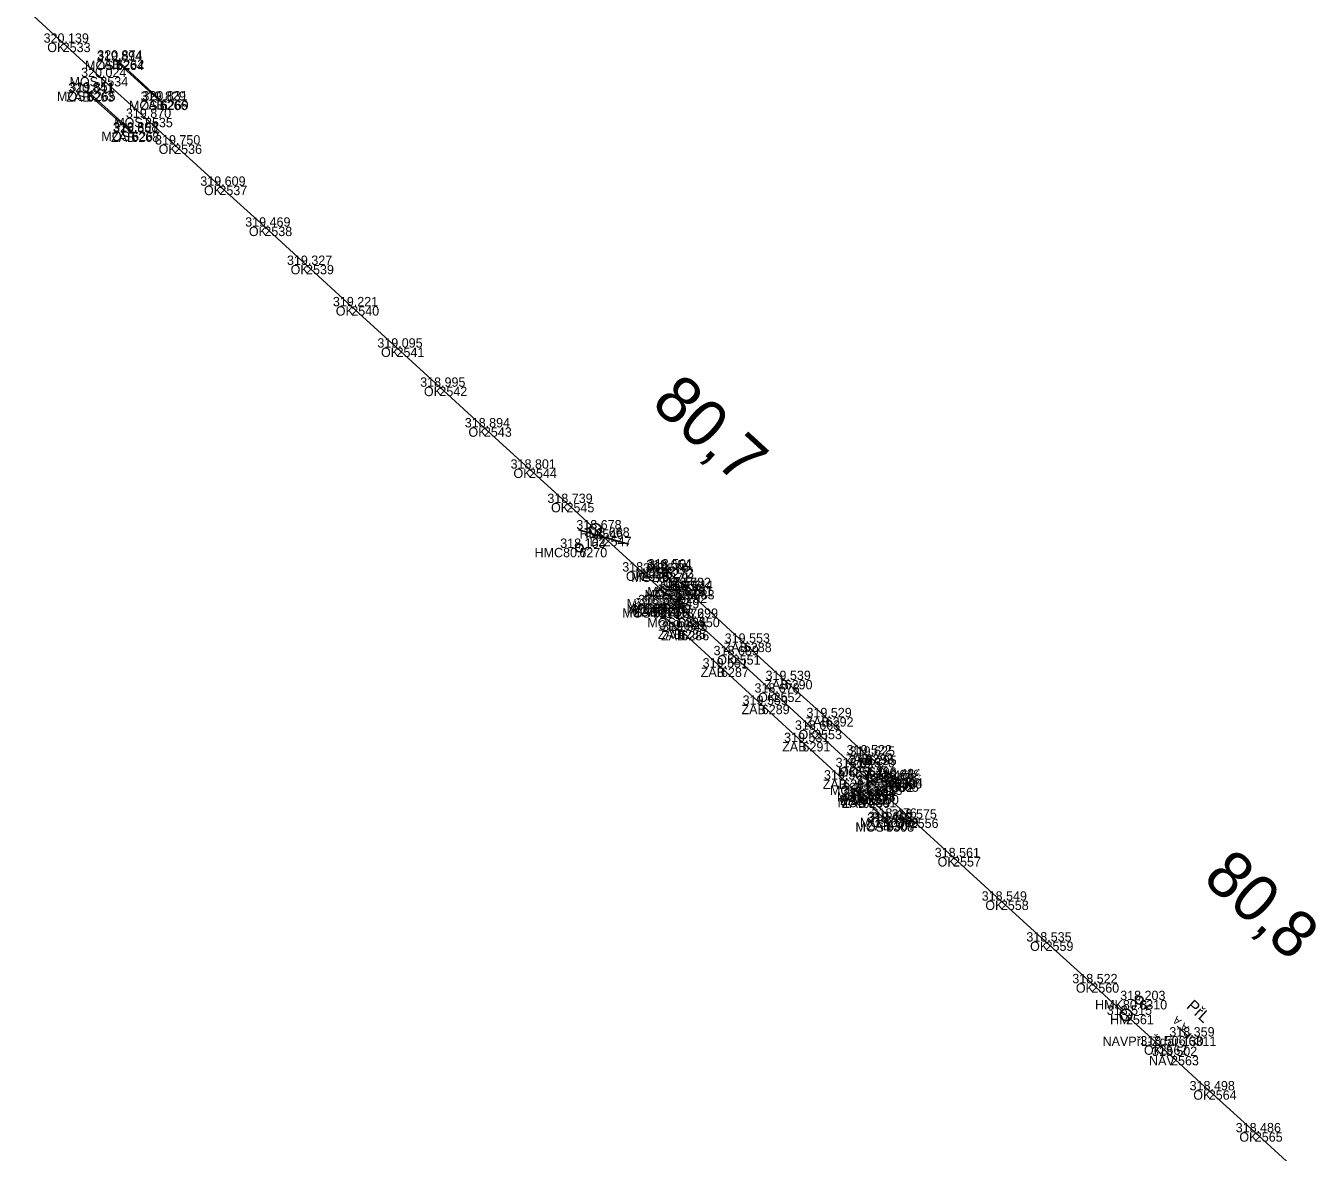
# Model space of a CAD drawing. Extents: x -621782 to -610392, y -1141853 to -1122321.
# Drawn here: x -614148.7 to -613983.2, y -1130727.2 to -1130582.8 of the extents above; entities that cross this region are included whole.
import ezdxf

# ---------------------------------------------------------------- set-up
doc = ezdxf.new("R2010")
doc.units = 0
for name, color, linetype in [('Vrstva 1', 7, 'Continuous'), ('Vrstva 17', 7, 'Continuous'), ('Vrstva 18', 7, 'Continuous'), ('Vrstva 3', 7, 'Continuous'), ('Vrstva 6', 7, 'Continuous'), ('Vrstva 60', 7, 'Continuous'), ('Vrstva 61', 7, 'Continuous'), ('Vrstva 62', 7, 'Continuous'), ('Vrstva 7', 7, 'Continuous')]:
    doc.layers.add(name, color=color, linetype=linetype)

msp = doc.modelspace()

# ---------------------------------------------------------------- linework, layer by layer
at = {"layer": 'Vrstva 1'}
msp.add_lwpolyline([(-614148.65, -1130580.61), (-614143.92, -1130584.95), (-614139.1, -1130589.35), (-614133.37, -1130594.58), (-614129.63, -1130598), (-614123.83, -1130603.29), (-614118.07, -1130608.53), (-614112.72, -1130613.44), (-614106.92, -1130618.74), (-614101.12, -1130624.04), (-614095.63, -1130629.06), (-614089.92, -1130634.27), (-614084.14, -1130639.56), (-614079.33, -1130643.96), (-614075.61, -1130647.35), (-614074.57, -1130648.3), (-614069.72, -1130652.75), (-614065.88, -1130656.27), (-614063.25, -1130658.68), (-614058.02, -1130663.48), (-614052.78, -1130668.28), (-614047.59, -1130673.04), (-614042.37, -1130677.84), (-614039.82, -1130680.19), (-614035.2, -1130684.43), (-614029.77, -1130689.38), (-614023.64, -1130694.95), (-614017.91, -1130700.19), (-614012.04, -1130705.54), (-614007.6, -1130709.59), (-614003.3, -1130713.51), (-614001.82, -1130714.86), (-613996.98, -1130719.27), (-613991.08, -1130724.65), (-613985.5, -1130729.75)], dxfattribs=at)
at = {"layer": 'Vrstva 17'}
for p, q in [((-614137.04, -1130587.11), (-614131.35, -1130592.35)), ((-614135.12, -1130596.46), (-614140.86, -1130591.31))]:
    msp.add_line(p, q, dxfattribs=at)
for points in [[(-614066.66, -1130652.45), (-614064.17, -1130654.74), (-614063.92, -1130655.12), (-614056.6, -1130661.88), (-614051.36, -1130666.66), (-614046.1, -1130671.43), (-614040.97, -1130676.2), (-614040.57, -1130676.37), (-614037.32, -1130679.37)], [(-614038.21, -1130684.75), (-614041.4, -1130681.85), (-614041.64, -1130681.47), (-614043.86, -1130679.42), (-614049.07, -1130674.62), (-614054.29, -1130669.84), (-614059.52, -1130665.06), (-614064.61, -1130660.37), (-614065.02, -1130660.19), (-614068.12, -1130657.34)]]:
    msp.add_lwpolyline(points, dxfattribs=at)
at = {"layer": 'Vrstva 18'}
for p, q in [((-614131.47, -1130592.39), (-614137.1, -1130587.25)), ((-614140.71, -1130591.21), (-614135.02, -1130596.34))]:
    msp.add_line(p, q, dxfattribs=at)
for points in [[(-614066.56, -1130652.36), (-614067.07, -1130652.89), (-614065.05, -1130654.75), (-614065.38, -1130655.11), (-614064.88, -1130655.58), (-614065.03, -1130658.7), (-614066.97, -1130656.92), (-614067.31, -1130657.28), (-614067.68, -1130656.94), (-614068.23, -1130657.46)], [(-614038.33, -1130684.9), (-614037.77, -1130684.31), (-614040.61, -1130681.77), (-614040.29, -1130681.4), (-614040.72, -1130681.03), (-614040.57, -1130677.86), (-614038.44, -1130679.81), (-614038.08, -1130679.45), (-614037.73, -1130679.79), (-614037.22, -1130679.25)]]:
    msp.add_lwpolyline(points, dxfattribs=at)
at = {"layer": 'Vrstva 3'}
msp.add_line((-614077.8, -1130647.39), (-614071.35, -1130649.22), dxfattribs=at)
at = {"layer": 'Vrstva 6'}
for p, q in [((-614001.05, -1130711.04), (-613999.58, -1130712.37)), ((-613999.92, -1130712.74), (-613999.25, -1130712))]:
    msp.add_line(p, q, dxfattribs=at)
at = {"layer": 'Vrstva 60'}
for p, q in [((-614143.92, -1130584.95), (-614143.92, -1130584.95)), ((-614137.1, -1130587.25), (-614137.1, -1130587.25)), ((-614137.04, -1130587.11), (-614137.04, -1130587.11)), ((-614139.1, -1130589.35), (-614139.1, -1130589.35)), ((-614140.86, -1130591.31), (-614140.86, -1130591.31)), ((-614140.71, -1130591.21), (-614140.71, -1130591.21)), ((-614131.47, -1130592.39), (-614131.47, -1130592.39)), ((-614131.35, -1130592.35), (-614131.35, -1130592.35)), ((-614133.37, -1130594.58), (-614133.37, -1130594.58)), ((-614135.12, -1130596.46), (-614135.12, -1130596.46)), ((-614135.02, -1130596.34), (-614135.02, -1130596.34)), ((-614129.63, -1130598), (-614129.63, -1130598)), ((-614123.83, -1130603.29), (-614123.83, -1130603.29)), ((-614118.07, -1130608.53), (-614118.07, -1130608.53)), ((-614112.72, -1130613.44), (-614112.72, -1130613.44)), ((-614106.92, -1130618.74), (-614106.92, -1130618.74)), ((-614101.12, -1130624.04), (-614101.12, -1130624.04)), ((-614095.63, -1130629.06), (-614095.63, -1130629.06)), ((-614089.92, -1130634.27), (-614089.92, -1130634.27)), ((-614084.14, -1130639.56), (-614084.14, -1130639.56)), ((-614079.33, -1130643.96), (-614079.33, -1130643.96)), ((-614075.61, -1130647.35), (-614075.61, -1130647.35)), ((-614074.57, -1130648.3), (-614074.57, -1130648.3)), ((-614077.68, -1130649.72), (-614077.68, -1130649.72)), ((-614066.66, -1130652.45), (-614066.66, -1130652.45)), ((-614066.56, -1130652.36), (-614066.56, -1130652.36)), ((-614069.72, -1130652.75), (-614069.72, -1130652.75)), ((-614067.07, -1130652.89), (-614067.07, -1130652.89)), ((-614065.38, -1130655.11), (-614065.38, -1130655.11)), ((-614065.05, -1130654.75), (-614065.05, -1130654.75)), ((-614064.88, -1130655.58), (-614064.88, -1130655.58)), ((-614064.17, -1130654.74), (-614064.17, -1130654.74)), ((-614063.92, -1130655.12), (-614063.92, -1130655.12)), ((-614068.23, -1130657.46), (-614068.23, -1130657.46)), ((-614068.12, -1130657.34), (-614068.12, -1130657.34)), ((-614067.68, -1130656.94), (-614067.68, -1130656.94)), ((-614067.31, -1130657.28), (-614067.31, -1130657.28)), ((-614066.97, -1130656.92), (-614066.97, -1130656.92)), ((-614065.88, -1130656.27), (-614065.88, -1130656.27)), ((-614065.03, -1130658.7), (-614065.03, -1130658.7)), ((-614063.25, -1130658.68), (-614063.25, -1130658.68)), ((-614065.02, -1130660.19), (-614065.02, -1130660.19)), ((-614064.61, -1130660.37), (-614064.61, -1130660.37)), ((-614056.6, -1130661.88), (-614056.6, -1130661.88)), ((-614058.02, -1130663.48), (-614058.02, -1130663.48)), ((-614059.52, -1130665.06), (-614059.52, -1130665.06)), ((-614051.36, -1130666.66), (-614051.36, -1130666.66)), ((-614052.78, -1130668.28), (-614052.78, -1130668.28)), ((-614054.29, -1130669.84), (-614054.29, -1130669.84)), ((-614046.1, -1130671.43), (-614046.1, -1130671.43)), ((-614047.59, -1130673.04), (-614047.59, -1130673.04)), ((-614049.07, -1130674.62), (-614049.07, -1130674.62)), ((-614040.97, -1130676.2), (-614040.97, -1130676.2)), ((-614040.57, -1130676.37), (-614040.57, -1130676.37)), ((-614042.37, -1130677.84), (-614042.37, -1130677.84)), ((-614040.57, -1130677.86), (-614040.57, -1130677.86)), ((-614043.86, -1130679.42), (-614043.86, -1130679.42)), ((-614039.82, -1130680.19), (-614039.82, -1130680.19)), ((-614038.44, -1130679.81), (-614038.44, -1130679.81)), ((-614038.08, -1130679.45), (-614038.08, -1130679.45)), ((-614037.73, -1130679.79), (-614037.73, -1130679.79)), ((-614037.32, -1130679.37), (-614037.32, -1130679.37)), ((-614037.22, -1130679.25), (-614037.22, -1130679.25)), ((-614041.64, -1130681.47), (-614041.64, -1130681.47)), ((-614041.4, -1130681.85), (-614041.4, -1130681.85)), ((-614040.72, -1130681.03), (-614040.72, -1130681.03)), ((-614040.61, -1130681.77), (-614040.61, -1130681.77)), ((-614040.29, -1130681.4), (-614040.29, -1130681.4)), ((-614038.33, -1130684.9), (-614038.33, -1130684.9)), ((-614038.21, -1130684.75), (-614038.21, -1130684.75)), ((-614037.77, -1130684.31), (-614037.77, -1130684.31)), ((-614035.2, -1130684.43), (-614035.2, -1130684.43)), ((-614029.77, -1130689.38), (-614029.77, -1130689.38)), ((-614023.64, -1130694.95), (-614023.64, -1130694.95)), ((-614017.91, -1130700.19), (-614017.91, -1130700.19)), ((-614012.04, -1130705.54), (-614012.04, -1130705.54)), ((-614005.89, -1130707.7), (-614005.89, -1130707.7)), ((-614007.6, -1130709.59), (-614007.6, -1130709.59)), ((-614003.3, -1130713.51), (-614003.3, -1130713.51)), ((-613999.58, -1130712.37), (-613999.58, -1130712.37)), ((-614001.82, -1130714.86), (-614001.82, -1130714.86)), ((-613996.98, -1130719.27), (-613996.98, -1130719.27)), ((-613991.08, -1130724.65), (-613991.08, -1130724.65))]:
    msp.add_line(p, q, dxfattribs=at)
at = {"layer": 'Vrstva 7'}
for p, q in [((-614077.72, -1130649.69), (-614077.64, -1130649.76)), ((-614005.93, -1130707.67), (-614005.85, -1130707.74))]:
    msp.add_line(p, q, dxfattribs=at)
for centre, radius in [((-614075.61, -1130647.35), 0.75), ((-614077.68, -1130649.72), 0.5), ((-614005.89, -1130707.7), 0.5), ((-614007.6, -1130709.59), 0.75)]:
    msp.add_circle(centre, radius, dxfattribs=at)

# ---------------------------------------------------------------- texts
at = {"layer": 'Vrstva 6'}
for s, height, rotation, p in [('PřL', 1.5, 317.7069, (-613999.94, -1130708.62)), ('  A A ', 1, 137.7069, (-613998.91, -1130711.63))]:
    msp.add_text(s, height=height, rotation=rotation, dxfattribs=at).set_placement(p)
at = {"layer": 'Vrstva 60'}
for s, p in [('2533', (-614143.92, -1130586.15)), ('6264', (-614137.1, -1130588.45)), ('6262', (-614137.04, -1130588.31)), ('2534', (-614139.1, -1130590.55)), ('6263', (-614140.86, -1130592.51)), ('6265', (-614140.71, -1130592.41)), ('6266', (-614131.47, -1130593.59)), ('6269', (-614131.35, -1130593.55)), ('2535', (-614133.37, -1130595.78)), ('6267', (-614135.02, -1130597.54)), ('6268', (-614135.12, -1130597.66)), ('2536', (-614129.63, -1130599.2)), ('2537', (-614123.83, -1130604.49)), ('2538', (-614118.07, -1130609.74)), ('2539', (-614112.72, -1130614.64)), ('2540', (-614106.92, -1130619.94)), ('2541', (-614101.12, -1130625.24)), ('2542', (-614095.63, -1130630.26)), ('2543', (-614089.92, -1130635.47)), ('2544', (-614084.14, -1130640.76)), ('2545', (-614079.33, -1130645.16)), ('2546', (-614075.61, -1130648.55)), ('2547', (-614074.57, -1130649.5)), ('6270', (-614077.68, -1130650.92)), ('6272', (-614066.66, -1130653.65)), ('6273', (-614066.56, -1130653.56)), ('2548', (-614069.72, -1130653.95)), ('6271', (-614067.07, -1130654.09)), ('6277', (-614065.38, -1130656.31)), ('6278', (-614065.05, -1130655.95)), ('6282', (-614064.88, -1130656.78)), ('6281', (-614064.17, -1130655.94)), ('6283', (-614063.92, -1130656.32)), ('6274', (-614068.23, -1130658.66)), ('6275', (-614068.12, -1130658.54)), ('6276', (-614067.68, -1130658.14)), ('6279', (-614067.31, -1130658.48)), ('6280', (-614066.97, -1130658.12)), ('2549', (-614065.88, -1130657.47)), ('6284', (-614065.03, -1130659.9)), ('2550', (-614063.25, -1130659.88)), ('6285', (-614065.02, -1130661.39)), ('6286', (-614064.61, -1130661.57)), ('6288', (-614056.6, -1130663.08)), ('2551', (-614058.02, -1130664.68)), ('6287', (-614059.52, -1130666.26)), ('6290', (-614051.36, -1130667.86)), ('2552', (-614052.78, -1130669.48)), ('6289', (-614054.29, -1130671.04)), ('6292', (-614046.1, -1130672.63)), ('2553', (-614047.59, -1130674.25)), ('6291', (-614049.07, -1130675.82)), ('6293', (-614040.97, -1130677.4)), ('6295', (-614040.57, -1130677.57)), ('2554', (-614042.37, -1130679.04)), ('6296', (-614040.57, -1130679.06)), ('6294', (-614043.86, -1130680.62)), ('2555', (-614039.82, -1130681.39)), ('6302', (-614038.44, -1130681.01)), ('6303', (-614038.08, -1130680.65)), ('6305', (-614037.73, -1130680.99)), ('6306', (-614037.32, -1130680.57)), ('6304', (-614037.22, -1130680.45)), ('6297', (-614041.64, -1130682.67)), ('6299', (-614041.4, -1130683.05)), ('6298', (-614040.72, -1130682.23)), ('6301', (-614040.61, -1130682.97)), ('6300', (-614040.29, -1130682.6)), ('6308', (-614038.33, -1130686.1)), ('6307', (-614038.21, -1130685.95)), ('6309', (-614037.77, -1130685.51)), ('2556', (-614035.2, -1130685.63)), ('2557', (-614029.77, -1130690.57)), ('2558', (-614023.64, -1130696.15)), ('2559', (-614017.91, -1130701.39)), ('2560', (-614012.04, -1130706.75)), ('6310', (-614005.89, -1130708.9)), ('2561', (-614007.6, -1130710.79)), ('2562', (-614003.3, -1130714.71)), ('6311', (-613999.58, -1130713.57)), ('2563', (-614001.82, -1130716.06)), ('2564', (-613996.98, -1130720.47)), ('2565', (-613991.08, -1130725.85))]:
    msp.add_text(s, height=1.2, dxfattribs=at).set_placement(p)
at = {"layer": 'Vrstva 61'}
for s, p in [('320.139', (-614146.37, -1130584.95)), ('319.894', (-614139.55, -1130587.25)), ('320.874', (-614139.49, -1130587.11)), ('320.024', (-614141.56, -1130589.35)), ('320.841', (-614143.22, -1130591.31)), ('319.851', (-614143.07, -1130591.21)), ('319.829', (-614133.93, -1130592.39)), ('320.831', (-614133.7, -1130592.35)), ('319.870', (-614135.82, -1130594.58)), ('320.851', (-614137.48, -1130596.46)), ('319.808', (-614137.47, -1130596.34)), ('319.750', (-614132.08, -1130598)), ('319.609', (-614126.28, -1130603.29)), ('319.469', (-614120.52, -1130608.53)), ('319.327', (-614115.17, -1130613.44)), ('319.221', (-614109.28, -1130618.74)), ('319.095', (-614103.58, -1130624.04)), ('318.995', (-614098.09, -1130629.06)), ('318.894', (-614092.37, -1130634.27)), ('318.801', (-614086.5, -1130639.56)), ('318.739', (-614081.78, -1130643.96)), ('318.678', (-614078.07, -1130647.35)), ('318.668', (-614077.03, -1130648.3)), ('318.163', (-614080.13, -1130649.72)), ('318.669', (-614072.18, -1130652.75)), ('318.570', (-614069.52, -1130652.89)), ('319.654', (-614069.11, -1130652.45)), ('318.501', (-614068.91, -1130652.36)), ('318.566', (-614067.83, -1130655.11)), ('318.578', (-614067.5, -1130654.75)), ('319.682', (-614066.62, -1130654.74)), ('319.544', (-614066.37, -1130655.12)), ('318.566', (-614070.14, -1130656.94)), ('318.565', (-614069.42, -1130656.92)), ('318.698', (-614068.33, -1130656.27)), ('318.573', (-614067.33, -1130655.58)), ('318.509', (-614070.69, -1130657.46)), ('319.659', (-614070.57, -1130657.34)), ('318.562', (-614069.76, -1130657.28)), ('318.572', (-614067.48, -1130658.7)), ('318.699', (-614065.7, -1130658.68)), ('319.680', (-614067.47, -1130660.19)), ('319.545', (-614067.07, -1130660.37)), ('319.553', (-614059.05, -1130661.88)), ('318.689', (-614060.47, -1130663.48)), ('319.551', (-614061.87, -1130665.06)), ('319.539', (-614053.81, -1130666.66)), ('318.678', (-614055.23, -1130668.28)), ('319.559', (-614056.75, -1130669.84)), ('319.529', (-614048.56, -1130671.43)), ('318.663', (-614050.04, -1130673.04)), ('319.531', (-614051.43, -1130674.62)), ('319.522', (-614043.42, -1130676.2)), ('319.625', (-614043.02, -1130676.37)), ('318.643', (-614044.82, -1130677.84)), ('318.520', (-614043.02, -1130677.86)), ('319.503', (-614046.32, -1130679.42)), ('318.631', (-614042.17, -1130680.19)), ('318.475', (-614040.9, -1130679.81)), ('318.475', (-614040.54, -1130679.45)), ('318.478', (-614040.18, -1130679.79)), ('319.618', (-614039.78, -1130679.37)), ('318.484', (-614039.67, -1130679.25)), ('319.522', (-614044.08, -1130681.47)), ('319.634', (-614043.85, -1130681.85)), ('318.511', (-614043.08, -1130681.03)), ('318.504', (-614043.06, -1130681.77)), ('318.510', (-614042.74, -1130681.4)), ('318.463', (-614040.78, -1130684.9)), ('319.602', (-614040.66, -1130684.75)), ('318.476', (-614040.22, -1130684.31)), ('318.575', (-614037.65, -1130684.43)), ('318.561', (-614032.12, -1130689.38)), ('318.549', (-614026.1, -1130694.95)), ('318.535', (-614020.37, -1130700.19)), ('318.522', (-614014.48, -1130705.54)), ('318.203', (-614008.34, -1130707.7)), ('318.515', (-614010.06, -1130709.59)), ('318.359', (-614002.04, -1130712.37)), ('318.506', (-614005.76, -1130713.51)), ('318.502', (-614004.27, -1130714.86)), ('318.498', (-613999.44, -1130719.27)), ('318.486', (-613993.53, -1130724.65))]:
    msp.add_text(s, height=1.2, dxfattribs=at).set_placement(p)
at = {"layer": 'Vrstva 62'}
for s, p in [('OK', (-614145.9, -1130586.15)), ('MOST', (-614141.05, -1130588.45)), ('ZAB', (-614139.64, -1130588.31)), ('MOST', (-614143.05, -1130590.55)), ('MOST', (-614144.66, -1130592.41)), ('ZAB', (-614143.46, -1130592.51)), ('MOST', (-614135.42, -1130593.59)), ('ZAB', (-614133.95, -1130593.55)), ('MOST', (-614137.32, -1130595.78)), ('MOST', (-614138.96, -1130597.54)), ('ZAB', (-614137.72, -1130597.66)), ('OK', (-614131.62, -1130599.2)), ('OK', (-614125.81, -1130604.49)), ('OK', (-614120.05, -1130609.74)), ('OK', (-614114.7, -1130614.64)), ('OK', (-614108.91, -1130619.94)), ('OK', (-614103.11, -1130625.24)), ('OK', (-614097.61, -1130630.26)), ('OK', (-614091.9, -1130635.47)), ('OK', (-614086.13, -1130640.76)), ('OK', (-614081.31, -1130645.16)), ('HM', (-614077.65, -1130648.55)), ('DZ', (-614076.37, -1130649.5)), ('HMC80.7', (-614083.42, -1130650.92)), ('MOST', (-614070.5, -1130653.56)), ('ZAB', (-614069.26, -1130653.65)), ('OK', (-614071.71, -1130653.95)), ('MOST', (-614071.01, -1130654.09)), ('MOST', (-614069.33, -1130656.31)), ('MOST', (-614068.99, -1130655.95)), ('MOST', (-614068.82, -1130656.78)), ('ZAB', (-614066.77, -1130655.94)), ('ZAB', (-614066.52, -1130656.32)), ('MOST', (-614072.18, -1130658.66)), ('MOST', (-614071.63, -1130658.14)), ('MOSTBS', (-614071.61, -1130657.47)), ('MOST', (-614071.26, -1130658.48)), ('MOST', (-614070.91, -1130658.12)), ('ZAB', (-614070.72, -1130658.54)), ('MOST', (-614068.97, -1130659.9)), ('OK', (-614065.23, -1130659.88)), ('ZAB', (-614067.62, -1130661.39)), ('ZAB', (-614067.21, -1130661.57)), ('ZAB', (-614059.2, -1130663.08)), ('OK', (-614060, -1130664.68)), ('ZAB', (-614062.12, -1130666.26)), ('ZAB', (-614053.96, -1130667.86)), ('OK', (-614054.76, -1130669.48)), ('ZAB', (-614056.89, -1130671.04)), ('ZAB', (-614048.7, -1130672.63)), ('OK', (-614049.58, -1130674.25)), ('ZAB', (-614051.68, -1130675.82)), ('ZAB', (-614043.57, -1130677.4)), ('ZAB', (-614043.17, -1130677.57)), ('MOST', (-614044.51, -1130679.06)), ('OK', (-614044.36, -1130679.04)), ('ZAB', (-614046.47, -1130680.62)), ('MOSTBS', (-614045.55, -1130681.39)), ('MOST', (-614042.39, -1130681.01)), ('MOST', (-614042.03, -1130680.65)), ('MOST', (-614041.67, -1130680.99)), ('MOST', (-614041.17, -1130680.45)), ('ZAB', (-614039.93, -1130680.57)), ('MOST', (-614044.67, -1130682.23)), ('MOST', (-614044.56, -1130682.97)), ('ZAB', (-614044.24, -1130682.67)), ('MOST', (-614044.24, -1130682.6)), ('ZAB', (-614044.01, -1130683.05)), ('MOST', (-614042.28, -1130686.1)), ('MOST', (-614041.72, -1130685.51)), ('ZAB', (-614040.81, -1130685.95)), ('OK', (-614037.18, -1130685.63)), ('OK', (-614031.75, -1130690.57)), ('OK', (-614025.63, -1130696.15)), ('OK', (-614019.89, -1130701.39)), ('OK', (-614014.02, -1130706.75)), ('HMK80.8', (-614011.56, -1130708.9)), ('HM', (-614009.63, -1130710.79)), ('NAVPřL-Žďár-130', (-614010.6, -1130713.57)), ('OK', (-614005.29, -1130714.71)), ('NAV', (-614004.64, -1130716.06)), ('OK', (-613998.97, -1130720.47)), ('OK', (-613993.06, -1130725.85))]:
    msp.add_text(s, height=1.2, dxfattribs=at).set_placement(p)
at = {"layer": 'Vrstva 7'}
for s, rotation, p in [('80,7', 317.6022, (-614068.63, -1130631.43)), ('80,8', 317.6203, (-613997.93, -1130692.34))]:
    msp.add_text(s, height=6, rotation=rotation, dxfattribs=at).set_placement(p)

doc.saveas('drawing.dxf')
